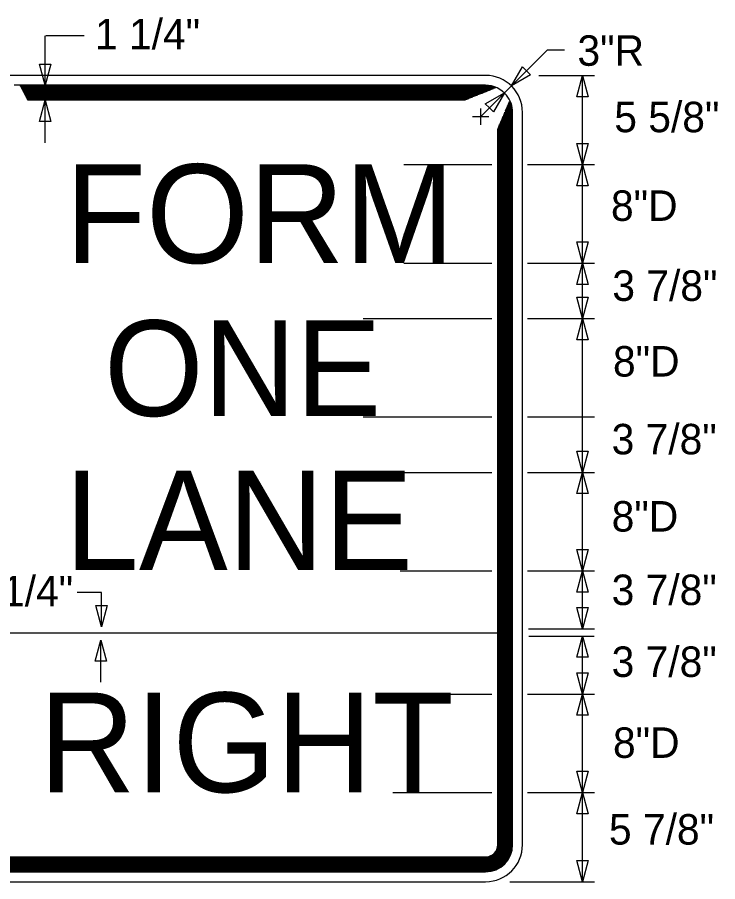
# Model space of a CAD drawing. Extents: x 15278 to 18126, y 1908 to 6555.
# Drawn here: x 17847.4 to 18040.4, y 2366.5 to 2604.8 of the extents above; entities that cross this region are included whole.
import ezdxf

# ---------------------------------------------------------------- set-up
doc = ezdxf.new("R2010")
doc.units = 0
for name, color, linetype in [('TYPICAL_EX', 7, 'Continuous'), ('TYPICAL_TEXT_DIMEN_EX', 7, 'Continuous'), ('TYPICAL_TEXT_DIMEN_PR', 7, 'Continuous')]:
    doc.layers.add(name, color=color, linetype=linetype)

msp = doc.modelspace()

# ---------------------------------------------------------------- linework, layer by layer
at = {"layer": 'TYPICAL_EX'}
for p, q in [((17976.4, 2588.82), (17833.88, 2588.82)), ((17976.4, 2586.1), (17846.51, 2586.1)), ((17976.4, 2585.99), (17848.04, 2585.99)), ((17976.4, 2585.88), (17848.18, 2585.88)), ((17976.4, 2585.77), (17848.24, 2585.77)), ((17976.4, 2585.66), (17848.29, 2585.66)), ((17976.4, 2585.54), (17848.35, 2585.54)), ((17976.4, 2585.43), (17848.41, 2585.43)), ((17976.4, 2585.32), (17848.47, 2585.32)), ((17976.4, 2585.21), (17848.53, 2585.21)), ((17976.4, 2585.1), (17848.58, 2585.1)), ((17976.4, 2584.98), (17848.64, 2584.98)), ((17976.4, 2584.87), (17848.7, 2584.87)), ((17976.4, 2584.76), (17848.76, 2584.76)), ((17976.4, 2584.65), (17848.82, 2584.65)), ((17976.4, 2584.53), (17848.87, 2584.53)), ((17976.4, 2584.42), (17848.93, 2584.42)), ((17976.4, 2584.31), (17848.99, 2584.31)), ((17976.26, 2584.2), (17849.05, 2584.2)), ((17975.99, 2584.09), (17849.1, 2584.09)), ((17975.7, 2583.97), (17849.16, 2583.97)), ((17975.42, 2583.86), (17849.22, 2583.86)), ((17975.14, 2583.75), (17849.28, 2583.75)), ((17974.86, 2583.64), (17849.34, 2583.64)), ((17974.58, 2583.53), (17849.4, 2583.53)), ((17974.3, 2583.41), (17849.45, 2583.41)), ((17974.02, 2583.3), (17849.51, 2583.3)), ((17973.74, 2583.19), (17849.57, 2583.19)), ((17973.46, 2583.08), (17849.63, 2583.08)), ((17973.18, 2582.97), (17849.69, 2582.97)), ((17972.9, 2582.85), (17849.74, 2582.85)), ((17972.62, 2582.74), (17849.8, 2582.74)), ((17972.34, 2582.63), (17849.86, 2582.63)), ((17972.06, 2582.52), (17849.92, 2582.52)), ((17971.78, 2582.41), (17849.97, 2582.41)), ((17971.49, 2582.29), (17850.03, 2582.29)), ((17971.21, 2582.18), (17850.09, 2582.18)), ((17970.93, 2582.07), (17850.15, 2582.07)), ((17970.75, 2581.99), (17850.19, 2581.99)), ((17980.73, 2430.59), (17980.73, 2576.31)), ((17980.84, 2430.48), (17980.84, 2576.57)), ((17980.95, 2430.5), (17980.95, 2576.83)), ((17981.06, 2430.55), (17981.06, 2577.09)), ((17981.17, 2430.59), (17981.17, 2577.35)), ((17981.28, 2430.53), (17981.28, 2577.61)), ((17981.4, 2430.55), (17981.4, 2577.87)), ((17981.51, 2430.53), (17981.51, 2578.13)), ((17981.62, 2430.42), (17981.62, 2578.39)), ((17981.73, 2430.57), (17981.73, 2578.64)), ((17981.84, 2430.59), (17981.84, 2578.64)), ((17981.96, 2430.57), (17981.96, 2578.64)), ((17982.07, 2430.46), (17982.07, 2578.64)), ((17982.18, 2430.53), (17982.18, 2578.64)), ((17982.29, 2430.59), (17982.29, 2578.64)), ((17982.4, 2430.63), (17982.4, 2578.64)), ((17982.52, 2430.55), (17982.52, 2578.64)), ((17982.63, 2430.59), (17982.63, 2578.64)), ((17982.74, 2430.55), (17982.74, 2578.64)), ((17982.85, 2430.57), (17982.85, 2578.64)), ((17982.97, 2430.57), (17982.97, 2578.64)), ((17983.08, 2430.57), (17983.08, 2578.64)), ((17983.19, 2430.61), (17983.19, 2578.64)), ((17983.3, 2430.63), (17983.3, 2578.64)), ((17983.41, 2430.57), (17983.41, 2578.64)), ((17983.53, 2430.57), (17983.53, 2578.64)), ((17983.64, 2430.61), (17983.64, 2578.64)), ((17983.75, 2430.57), (17983.75, 2578.64)), ((17983.86, 2430.62), (17983.86, 2578.64)), ((17986.58, 2430.6), (17986.58, 2578.64)), ((17979.75, 2430.55), (17979.75, 2574.06)), ((17979.83, 2430.55), (17979.83, 2574.23)), ((17979.94, 2430.65), (17979.94, 2574.49)), ((17980.05, 2430.63), (17980.05, 2574.75)), ((17980.16, 2430.55), (17980.16, 2575.01)), ((17980.28, 2430.55), (17980.28, 2575.27)), ((17980.39, 2430.63), (17980.39, 2575.53)), ((17980.5, 2430.48), (17980.5, 2575.79)), ((17980.61, 2430.57), (17980.61, 2576.05)), ((17830.94, 2435.12), (17979.69, 2435.12)), ((17979.75, 2376.7), (17979.75, 2430.55)), ((17979.83, 2376.7), (17979.83, 2430.55)), ((17979.94, 2376.7), (17979.94, 2430.55)), ((17980.05, 2376.7), (17980.05, 2430.55)), ((17980.16, 2376.7), (17980.16, 2430.55)), ((17980.28, 2376.7), (17980.28, 2430.55)), ((17980.39, 2376.7), (17980.39, 2430.55)), ((17980.5, 2376.7), (17980.5, 2430.55)), ((17980.61, 2376.7), (17980.61, 2430.55)), ((17980.72, 2376.7), (17980.72, 2430.55)), ((17980.84, 2376.7), (17980.84, 2430.55)), ((17980.95, 2376.7), (17980.95, 2430.55)), ((17981.06, 2376.7), (17981.06, 2430.55)), ((17981.17, 2376.7), (17981.17, 2430.55)), ((17981.28, 2376.7), (17981.28, 2430.55)), ((17981.4, 2376.7), (17981.4, 2430.55)), ((17981.51, 2376.7), (17981.51, 2430.55)), ((17981.62, 2376.7), (17981.62, 2430.55)), ((17981.73, 2376.7), (17981.73, 2430.55)), ((17981.84, 2376.7), (17981.84, 2430.55)), ((17981.96, 2376.7), (17981.96, 2430.55)), ((17982.07, 2376.7), (17982.07, 2430.55)), ((17982.18, 2376.7), (17982.18, 2430.55)), ((17982.29, 2376.7), (17982.29, 2430.55)), ((17982.4, 2376.7), (17982.4, 2430.55)), ((17982.52, 2376.7), (17982.52, 2430.55)), ((17982.63, 2376.7), (17982.63, 2430.55)), ((17982.74, 2376.7), (17982.74, 2430.55)), ((17982.85, 2376.7), (17982.85, 2430.55)), ((17982.97, 2376.7), (17982.97, 2430.55)), ((17983.08, 2376.7), (17983.08, 2430.55)), ((17983.19, 2376.7), (17983.19, 2430.55)), ((17983.3, 2376.7), (17983.3, 2430.55)), ((17983.41, 2376.7), (17983.41, 2430.55)), ((17983.53, 2376.7), (17983.53, 2430.55)), ((17983.64, 2376.7), (17983.64, 2430.55)), ((17983.75, 2376.7), (17983.75, 2430.55)), ((17983.86, 2376.7), (17983.86, 2430.55)), ((17986.58, 2376.7), (17986.58, 2430.55)), ((17833.88, 2373.35), (17976.4, 2373.35)), ((17833.88, 2373.27), (17976.4, 2373.27)), ((17833.88, 2373.16), (17976.4, 2373.16)), ((17833.88, 2373.05), (17976.4, 2373.05)), ((17833.88, 2372.94), (17976.4, 2372.94)), ((17833.88, 2372.83), (17976.4, 2372.83)), ((17833.88, 2372.71), (17976.4, 2372.71)), ((17833.88, 2372.6), (17976.4, 2372.6)), ((17833.88, 2372.49), (17976.4, 2372.49)), ((17833.88, 2372.38), (17976.4, 2372.38)), ((17833.88, 2372.27), (17976.4, 2372.27)), ((17833.88, 2372.15), (17976.4, 2372.15)), ((17833.88, 2372.04), (17976.4, 2372.04)), ((17833.88, 2371.93), (17976.4, 2371.93)), ((17833.88, 2371.82), (17976.4, 2371.82)), ((17833.88, 2371.7), (17976.4, 2371.7)), ((17833.88, 2371.59), (17976.4, 2371.59)), ((17833.88, 2371.48), (17976.4, 2371.48)), ((17833.88, 2371.37), (17976.4, 2371.37)), ((17833.88, 2371.26), (17976.4, 2371.26)), ((17833.88, 2371.14), (17976.4, 2371.14)), ((17833.88, 2371.03), (17976.4, 2371.03)), ((17833.88, 2370.92), (17976.4, 2370.92)), ((17833.88, 2370.81), (17976.4, 2370.81)), ((17833.88, 2370.7), (17976.4, 2370.7)), ((17833.88, 2370.59), (17976.4, 2370.59)), ((17833.88, 2370.47), (17976.4, 2370.47)), ((17833.88, 2370.36), (17976.4, 2370.36)), ((17833.88, 2370.25), (17976.4, 2370.25)), ((17833.88, 2370.14), (17976.4, 2370.14)), ((17833.88, 2370.02), (17976.4, 2370.02)), ((17833.88, 2369.91), (17976.4, 2369.91)), ((17833.88, 2369.8), (17976.4, 2369.8)), ((17833.88, 2369.69), (17976.4, 2369.69)), ((17833.88, 2369.58), (17976.4, 2369.58)), ((17833.88, 2369.46), (17976.4, 2369.46)), ((17833.88, 2369.35), (17976.4, 2369.35)), ((17833.88, 2369.24), (17976.4, 2369.24)), ((17833.88, 2366.53), (17976.4, 2366.53))]:
    msp.add_line(p, q, dxfattribs=at)
for centre, radius, start, end in [((17976.4, 2578.64), 10.18, 0, 90), ((17976.4, 2578.64), 7.46, 39.0673, 90), ((17976.4, 2578.64), 7.35, 66.9087, 90), ((17976.4, 2578.64), 7.24, 67.8069, 90), ((17976.4, 2578.64), 7.13, 68.7489, 90), ((17976.4, 2578.64), 7.02, 69.7388, 90), ((17976.4, 2578.64), 6.9, 70.7811, 90), ((17976.4, 2578.64), 6.79, 71.8812, 90), ((17976.4, 2578.64), 6.68, 73.0455, 90), ((17976.4, 2578.64), 6.57, 74.2814, 90), ((17976.4, 2578.64), 6.46, 75.5979, 90), ((17976.4, 2578.64), 6.34, 77.006, 90), ((17976.4, 2578.64), 6.23, 78.5194, 90), ((17976.4, 2578.64), 6.12, 80.1555, 90), ((17976.4, 2578.64), 6.01, 81.9371, 90), ((17976.4, 2578.64), 5.9, 83.8949, 90), ((17976.4, 2578.64), 5.78, 86.0727, 90), ((17976.4, 2578.64), 5.67, 88.5362, 90), ((17976.4, 2578.64), 7.46, 0, 39.0664), ((17976.4, 2578.64), 6.9, 0, 21.5151), ((17976.4, 2578.64), 7.02, 0, 22.4279), ((17976.4, 2578.64), 7.13, 0, 23.2988), ((17976.4, 2578.64), 7.24, 0, 24.1309), ((17976.4, 2578.64), 7.35, 0, 24.1308), ((17976.4, 2578.64), 5.45, 0, 2.6891), ((17976.4, 2578.64), 5.56, 0, 4.9634), ((17976.4, 2578.64), 5.67, 0, 6.9999), ((17976.4, 2578.64), 5.78, 0, 8.847), ((17976.4, 2578.64), 5.9, 0, 10.5386), ((17976.4, 2578.64), 6.01, 0, 12.0996), ((17976.4, 2578.64), 6.12, 0, 13.5489), ((17976.4, 2578.64), 6.23, 0, 14.9011), ((17976.4, 2578.64), 6.34, 0, 16.1683), ((17976.4, 2578.64), 6.46, 0, 17.36), ((17976.4, 2578.64), 6.57, 0, 18.4842), ((17976.4, 2578.64), 6.68, 0, 19.5478), ((17976.4, 2578.64), 6.79, 0, 20.5564), ((17976.4, 2578.64), 5.34, 0, 0.1031), ((17976.4, 2376.71), 7.46, 270, 0), ((17976.4, 2376.71), 3.36, 270, 0), ((17976.4, 2376.71), 7.35, 270, 0), ((17976.4, 2376.71), 7.24, 270, 0), ((17976.4, 2376.71), 7.13, 270, 0), ((17976.4, 2376.71), 7.02, 270, 0), ((17976.4, 2376.71), 6.9, 270, 0), ((17976.4, 2376.71), 6.79, 270, 0), ((17976.4, 2376.71), 6.68, 270, 0), ((17976.4, 2376.71), 6.57, 270, 0), ((17976.4, 2376.71), 6.46, 270, 0), ((17976.4, 2376.71), 6.34, 270, 0), ((17976.4, 2376.71), 6.23, 270, 0), ((17976.4, 2376.71), 6.12, 270, 0), ((17976.4, 2376.71), 6.01, 270, 0), ((17976.4, 2376.71), 5.9, 270, 0), ((17976.4, 2376.71), 5.78, 270, 0), ((17976.4, 2376.71), 5.67, 270, 0), ((17976.4, 2376.71), 5.56, 270, 0), ((17976.4, 2376.71), 5.45, 270, 0), ((17976.4, 2376.71), 5.34, 270, 0), ((17976.4, 2376.71), 5.22, 270, 0), ((17976.4, 2376.71), 5.11, 270, 0), ((17976.4, 2376.71), 5, 270, 0), ((17976.4, 2376.71), 4.89, 270, 0), ((17976.4, 2376.71), 4.78, 270, 0), ((17976.4, 2376.71), 4.66, 270, 0), ((17976.4, 2376.71), 4.55, 270, 0), ((17976.4, 2376.71), 4.44, 270, 0), ((17976.4, 2376.71), 4.33, 270, 0), ((17976.4, 2376.71), 4.21, 270, 0), ((17976.4, 2376.71), 4.1, 270, 0), ((17976.4, 2376.71), 3.99, 270, 0), ((17976.4, 2376.71), 3.88, 270, 0), ((17976.4, 2376.71), 3.77, 270, 0), ((17976.4, 2376.71), 3.65, 270, 0), ((17976.4, 2376.71), 3.54, 270, 0), ((17976.4, 2376.71), 3.43, 270, 0), ((17976.4, 2376.71), 10.18, 270, 0)]:
    msp.add_arc(centre, radius, start, end, dxfattribs=at)
at = {"layer": 'TYPICAL_TEXT_DIMEN_PR'}
for p, q in [((17855.03, 2586.1), (17855.03, 2599.74)), ((17855.2, 2599.81), (17865.77, 2599.81)), ((17983.51, 2585.92), (17993.46, 2595.88)), ((17993.46, 2595.88), (17998.17, 2595.88)), ((17855.03, 2586.1), (17853.46, 2591.97)), ((17853.46, 2591.97), (17855.03, 2591.97)), ((17855.03, 2591.97), (17856.6, 2591.97)), ((17856.6, 2591.97), (17855.03, 2586.1)), ((17983.51, 2585.92), (17986.54, 2591.18)), ((17986.54, 2591.18), (17987.65, 2590.07)), ((17988.76, 2588.96), (17983.51, 2585.92)), ((17987.65, 2590.07), (17988.76, 2588.96)), ((17991.1, 2588.82), (18006.46, 2588.82)), ((18001.57, 2582.96), (18003.14, 2588.82)), ((18003.14, 2564.22), (18003.14, 2588.82)), ((18003.14, 2588.82), (18004.71, 2582.96)), ((17855.03, 2586.36), (17855.03, 2586.37)), ((17855.03, 2586.36), (17855.03, 2586.36)), ((17981.59, 2584.01), (17983.48, 2585.89)), ((17975.06, 2577.48), (17981.59, 2584.01)), ((17976.33, 2580.97), (17981.59, 2584)), ((17981.59, 2584), (17978.55, 2578.75)), ((17853.46, 2576.13), (17855.03, 2581.99)), ((17855.03, 2570.22), (17855.03, 2581.99)), ((17855.03, 2581.99), (17856.6, 2576.13)), ((18003.14, 2582.96), (18001.57, 2582.96)), ((18004.71, 2582.96), (18003.14, 2582.96)), ((17975.06, 2575.24), (17975.06, 2579.72)), ((17977.44, 2579.86), (17976.33, 2580.97)), ((17978.55, 2578.75), (17977.44, 2579.86)), ((17972.82, 2577.48), (17975.06, 2577.48)), ((17975.06, 2577.48), (17977.3, 2577.48)), ((17855.03, 2576.13), (17853.46, 2576.13)), ((17856.6, 2576.13), (17855.03, 2576.13)), ((18003.14, 2564.22), (18001.57, 2570.08)), ((18001.57, 2570.08), (18003.14, 2570.08)), ((18003.14, 2570.08), (18004.71, 2570.08)), ((18004.71, 2570.08), (18003.14, 2564.22)), ((17953.92, 2564.22), (17978.09, 2564.22)), ((17987.94, 2564.22), (18006.46, 2564.22)), ((18001.57, 2558.36), (18003.14, 2564.22)), ((18003.14, 2537.07), (18003.14, 2564.22)), ((18003.14, 2564.22), (18004.71, 2558.36)), ((18003.14, 2558.36), (18001.57, 2558.36)), ((18004.71, 2558.36), (18003.14, 2558.36)), ((18003.14, 2537.07), (18001.57, 2542.94)), ((18001.57, 2542.94), (18003.14, 2542.94)), ((18003.14, 2542.94), (18004.71, 2542.94)), ((18004.71, 2542.94), (18003.14, 2537.07)), ((17953.92, 2537.07), (17978.09, 2537.07)), ((17987.94, 2537.07), (18006.46, 2537.07)), ((18001.57, 2531.21), (18003.14, 2537.07)), ((18003.14, 2521.8), (18003.14, 2537.07)), ((18003.14, 2537.07), (18004.71, 2531.21)), ((18003.14, 2531.21), (18001.57, 2531.21)), ((18004.71, 2531.21), (18003.14, 2531.21)), ((18003.14, 2521.8), (18001.57, 2527.67)), ((18001.57, 2527.67), (18003.14, 2527.67)), ((18003.14, 2527.67), (18004.71, 2527.67)), ((18004.71, 2527.67), (18003.14, 2521.8)), ((17942.66, 2521.8), (17978.09, 2521.8)), ((17987.94, 2521.8), (18006.46, 2521.8)), ((18001.57, 2515.94), (18003.14, 2521.8)), ((18003.14, 2494.66), (18003.14, 2521.8)), ((18003.14, 2521.8), (18004.71, 2515.94)), ((18003.14, 2515.94), (18001.57, 2515.94)), ((18004.71, 2515.94), (18003.14, 2515.94)), ((17942.66, 2494.66), (17978.09, 2494.66)), ((17987.94, 2494.66), (18006.46, 2494.66)), ((18003.14, 2479.39), (18003.14, 2494.66)), ((18003.14, 2479.39), (18001.57, 2485.25)), ((18001.57, 2485.25), (18003.14, 2485.25)), ((18003.14, 2485.25), (18004.71, 2485.25)), ((18004.71, 2485.25), (18003.14, 2479.39)), ((17952.91, 2479.39), (17978.09, 2479.39)), ((17987.94, 2479.39), (18006.46, 2479.39)), ((18001.57, 2473.53), (18003.14, 2479.39)), ((18003.14, 2452.24), (18003.14, 2479.39)), ((18003.14, 2479.39), (18004.71, 2473.53)), ((18003.14, 2473.53), (18001.57, 2473.53)), ((18004.71, 2473.53), (18003.14, 2473.53)), ((18003.14, 2452.24), (18001.57, 2458.11)), ((18001.57, 2458.11), (18003.14, 2458.11)), ((18003.14, 2458.11), (18004.71, 2458.11)), ((18004.71, 2458.11), (18003.14, 2452.24)), ((17952.91, 2452.24), (17978.09, 2452.24)), ((17987.94, 2452.24), (18006.46, 2452.24)), ((18001.57, 2446.38), (18003.14, 2452.24)), ((18003.14, 2436.27), (18003.14, 2452.24)), ((18003.14, 2452.24), (18003.14, 2452.24)), ((18003.14, 2452.24), (18003.14, 2452.24)), ((18003.14, 2452.24), (18004.71, 2446.38)), ((17870.56, 2446.28), (17863.9, 2446.28)), ((17870.56, 2436.83), (17870.56, 2446.28)), ((18003.14, 2446.38), (18001.57, 2446.38)), ((18004.71, 2446.38), (18003.14, 2446.38)), ((17870.56, 2436.83), (17868.99, 2442.69)), ((17868.99, 2442.69), (17870.56, 2442.69)), ((17870.56, 2442.69), (17872.13, 2442.69)), ((17872.13, 2442.69), (17870.56, 2436.83)), ((18003.14, 2436.27), (18001.57, 2442.13)), ((18001.57, 2442.13), (18003.14, 2442.13)), ((18003.14, 2442.13), (18004.71, 2442.13)), ((18004.71, 2442.13), (18003.14, 2436.27)), ((17988.19, 2436.27), (18006.38, 2436.27)), ((17988.29, 2434.26), (18006.28, 2434.26)), ((18001.57, 2428.39), (18003.14, 2434.25)), ((18003.14, 2418.27), (18003.14, 2434.25)), ((18003.14, 2434.25), (18004.71, 2428.39)), ((17868.82, 2427.3), (17870.39, 2433.16)), ((17870.39, 2421.51), (17870.39, 2433.16)), ((17870.39, 2433.16), (17871.96, 2427.3)), ((18004.36, 2430.55), (18004.36, 2430.54)), ((17870.39, 2427.3), (17868.82, 2427.3)), ((17871.96, 2427.3), (17870.39, 2427.3)), ((18003.14, 2428.39), (18001.57, 2428.39)), ((18004.71, 2428.39), (18003.14, 2428.39)), ((18003.14, 2418.27), (18001.57, 2424.13)), ((18001.57, 2424.13), (18003.14, 2424.13)), ((18003.14, 2424.13), (18004.71, 2424.13)), ((18004.71, 2424.13), (18003.14, 2418.27)), ((17958.23, 2418.27), (17978.09, 2418.27)), ((17987.94, 2418.27), (18006.46, 2418.27)), ((18001.57, 2412.41), (18003.14, 2418.27)), ((18003.14, 2391.12), (18003.14, 2418.27)), ((18003.14, 2418.27), (18004.71, 2412.41)), ((18003.14, 2412.41), (18001.57, 2412.41)), ((18004.71, 2412.41), (18003.14, 2412.41)), ((18003.14, 2391.12), (18001.57, 2396.99)), ((18001.57, 2396.99), (18003.14, 2396.99)), ((18003.14, 2396.99), (18004.71, 2396.99)), ((18004.71, 2396.99), (18003.14, 2391.12)), ((17950.81, 2391.12), (17978.09, 2391.12)), ((17987.94, 2391.12), (18006.46, 2391.12)), ((18001.57, 2385.26), (18003.14, 2391.12)), ((18003.14, 2366.53), (18003.14, 2391.12)), ((18003.14, 2391.12), (18004.71, 2385.26)), ((18003.14, 2385.26), (18001.57, 2385.26)), ((18004.71, 2385.26), (18003.14, 2385.26)), ((18003.14, 2366.53), (18001.57, 2372.39)), ((18001.57, 2372.39), (18003.14, 2372.39)), ((18003.14, 2372.39), (18004.71, 2372.39)), ((18004.71, 2372.39), (18003.14, 2366.53)), ((17983.09, 2366.53), (18006.46, 2366.53))]:
    msp.add_line(p, q, dxfattribs=at)

# ---------------------------------------------------------------- texts
at = {"layer": 'TYPICAL_TEXT_DIMEN_EX'}
for s, height, p in [('FORM', 27.241, (17860.6, 2537.08)), ('ONE', 26.355, (17871.29, 2494.93)), ('LANE', 27.463, (17860.46, 2452.42)), ('RIGHT', 27.463, (17853.39, 2391.2))]:
    msp.add_text(s, height=height, dxfattribs=at).set_placement(p)
at = {"layer": 'TYPICAL_TEXT_DIMEN_PR'}
for s, p in [('1 1/4"', (17868.78, 2596)), ('3"R', (18001.72, 2591.48)), ('5 5/8"', (18011.87, 2573.16)), ('8"D', (18010.96, 2548.72)), ('3 7/8"', (18011.33, 2526.66)), ('8"D', (18011.51, 2505.8)), ('3 7/8"', (18011.14, 2484.35)), ('8"D', (18011.15, 2463.06)), ('1 1/4"', (17833.8, 2442.45)), ('3 7/8"', (18011.14, 2442.8)), ('3 7/8"', (18011.14, 2422.98)), ('8"D', (18011.51, 2400.67)), ('5 7/8"', (18010.4, 2376.76))]:
    msp.add_text(s, height=8.4, dxfattribs=at).set_placement(p)

doc.saveas('drawing.dxf')
